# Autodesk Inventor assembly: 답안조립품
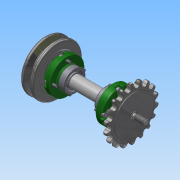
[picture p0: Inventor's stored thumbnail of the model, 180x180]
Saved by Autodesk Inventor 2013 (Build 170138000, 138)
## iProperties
Created: 2016-03
Part Number: 답안조립품
Document SubType Name: Assembly
Designer: Administrator
Author: Administrator
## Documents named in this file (10)
- C:\Users\Administrator\Desktop\460307V1014\답안조립품.iam
- C:\Users\Administrator\Desktop\460307V1014\1-본체.ipt
- C:\Users\Administrator\Desktop\460307V1014\베어링 15 x 32 x 9.ipt
- C:\Users\Administrator\Desktop\460307V1014\커버.ipt
- C:\Users\Administrator\Desktop\460307V1014\오일 실 15 25 7.ipt
- C:\Users\Administrator\Desktop\460307V1014\축.ipt
- C:\Users\Administrator\Desktop\460307V1014\볼트 M4 x 12.ipt
- C:\Users\Administrator\Desktop\460307V1014\키 3 x 3 x 12.ipt
- C:\Users\Administrator\Desktop\460307V1014\스프로킷.ipt
- C:\Users\Administrator\Desktop\460307V1014\V벨트풀리.ipt
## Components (12 placed, 4 different names)
1. 1-본체:1
2. KS B 2023 6002 - 15 x 32 x 9:1
3. KS B 2023 6002 - 15 x 32 x 9:2
4. V벨트풀리:1 — 각도:2
5. ISO 4762 M4 x 12:2
6. ISO 4762 M4 x 12:3
7. ISO 4762 M4 x 12:4
8. ISO 4762 M4 x 12:5
9. ISO 4762 M4 x 12:1
10. ISO 4762 M4 x 12:6
11. ISO 4762 M4 x 12:7
12. ISO 4762 M4 x 12:8
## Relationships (1: Angle 1)
- 각도:2 [Angle]: V벨트풀리:1
